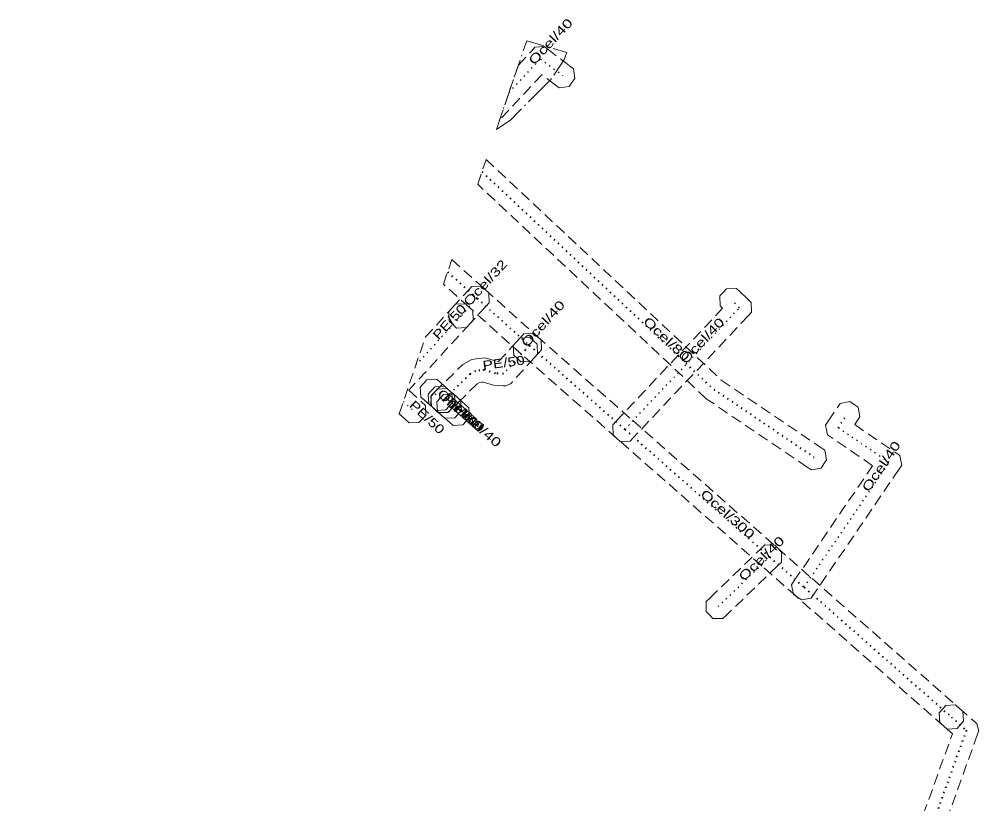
# Model space of a CAD drawing. Extents: x -644301 to -644150, y -1042432 to -1042139.
# Drawn here: x -644293 to -644212.5, y -1042204.6 to -1042138.8 of the extents above; entities that cross this region are included whole.
import ezdxf

# ---------------------------------------------------------------- set-up
doc = ezdxf.new("R2010")
doc.units = 0
doc.header["$LTSCALE"] = 0.3
for name, pattern in [('DOT_DASHED', [7.7, 5, -1.2, 0.3, -1.2]), ('DOTTED', [1.5, 0.3, -1.2]), ('MEDIUM_DASHED', [4.5, 3, -1.5])]:
    doc.linetypes.add(name, pattern=pattern)
for name, color, linetype, lineweight in [('1', 7, 'MEDIUM_DASHED', 13), ('18', 7, 'DOTTED', 25), ('3', 7, 'DOT_DASHED', 13)]:
    doc.layers.add(name, color=color, linetype=linetype, lineweight=lineweight)
doc.layers.add('20', color=7, linetype='Continuous')

msp = doc.modelspace()

# ---------------------------------------------------------------- linework, layer by layer
at = {"layer": '1'}
for points in [[(-644249.115, -1042143.464), (-644252.666, -1042147.268), (-644251.086, -1042142.644), (-644249.963, -1042141.441), (-644249.701, -1042141.16), (-644248.937, -1042141.094), (-644248.63, -1042141.325), (-644246.79, -1042142.713), (-644246.459, -1042142.962), (-644246.344, -1042143.782), (-644246.594, -1042144.113), (-644246.843, -1042144.444), (-644247.663, -1042144.559), (-644247.994, -1042144.309)], [(-644235.331, -1042170.644), (-644254.504, -1042152.644), (-644253.794, -1042150.568), (-644234.077, -1042169.078), (-644225.728, -1042174.736), (-644225.385, -1042174.968), (-644225.229, -1042175.782), (-644225.461, -1042176.125), (-644225.693, -1042176.468), (-644226.507, -1042176.624), (-644226.85, -1042176.392)], [(-644255.22, -1042162.968), (-644257.371, -1042161.031), (-644256.667, -1042158.974), (-644253.882, -1042161.482), (-644249.504, -1042165.424), (-644241.501, -1042172.475), (-644229.358, -1042183.173), (-644226.458, -1042185.728), (-644214.106, -1042196.61), (-644213.795, -1042196.884), (-644213.743, -1042197.71), (-644214.017, -1042198.021), (-644214.291, -1042198.332), (-644215.117, -1042198.384), (-644215.428, -1042198.11), (-644227.78, -1042187.228), (-644230.68, -1042184.673), (-644242.823, -1042173.975), (-644250.834, -1042166.918)], [(-644253.535, -1042162.597), (-644253.815, -1042162.902), (-644255.168, -1042164.374), (-644255.448, -1042164.679), (-644256.276, -1042164.713), (-644256.581, -1042164.433), (-644256.886, -1042164.153), (-644256.92, -1042163.325), (-644256.64, -1042163.02), (-644255.287, -1042161.548), (-644255.007, -1042161.243), (-644254.179, -1042161.209), (-644253.874, -1042161.489), (-644253.569, -1042161.769)], [(-644242.89, -1042172.54), (-644233.955, -1042163.05), (-644234.166, -1042162.852), (-644234.19, -1042162.024), (-644233.906, -1042161.722), (-644233.622, -1042161.42), (-644232.794, -1042161.396), (-644232.492, -1042161.68), (-644231.856, -1042162.279), (-644231.555, -1042162.563), (-644231.53, -1042163.391), (-644231.814, -1042163.692), (-644241.434, -1042173.91), (-644241.718, -1042174.212), (-644242.545, -1042174.237), (-644242.847, -1042173.953), (-644243.149, -1042173.669), (-644243.174, -1042172.842)], [(-644260.559, -1042172.397), (-644261.087, -1042171.906), (-644258.885, -1042165.462), (-644256.64, -1042163.02), (-644256.36, -1042162.715), (-644255.532, -1042162.681), (-644255.227, -1042162.961), (-644254.922, -1042163.241), (-644254.888, -1042164.069), (-644255.168, -1042164.374), (-644260.275, -1042169.93), (-644259.197, -1042170.933), (-644258.894, -1042171.215), (-644258.864, -1042172.043), (-644259.146, -1042172.346), (-644259.428, -1042172.649), (-644260.256, -1042172.679)], [(-644249.486, -1042166.906), (-644249.765, -1042167.213), (-644251.593, -1042169.227), (-644251.743, -1042169.392), (-644252.155, -1042169.564), (-644252.378, -1042169.554), (-644253.177, -1042169.518), (-644254.057, -1042169.245), (-644254.185, -1042169.262), (-644254.356, -1042169.285), (-644254.547, -1042169.392), (-644256.716, -1042171.522), (-644257.012, -1042171.812), (-644257.84, -1042171.805), (-644258.13, -1042171.51), (-644258.42, -1042171.214), (-644258.413, -1042170.386), (-644258.118, -1042170.096), (-644255.757, -1042167.776), (-644254.998, -1042167.353), (-644254.449, -1042167.28), (-644253.885, -1042167.205), (-644252.831, -1042167.532), (-644252.758, -1042167.535), (-644251.245, -1042165.869), (-644250.967, -1042165.562), (-644250.14, -1042165.522), (-644249.833, -1042165.801), (-644249.526, -1042166.079)], [(-644249.15, -1042166.536), (-644249.429, -1042166.843), (-644249.765, -1042167.213), (-644250.043, -1042167.52), (-644250.87, -1042167.56), (-644251.177, -1042167.281), (-644251.484, -1042167.003), (-644251.524, -1042166.176), (-644251.245, -1042165.869), (-644250.909, -1042165.499), (-644250.631, -1042165.192), (-644249.804, -1042165.152), (-644249.497, -1042165.431), (-644249.19, -1042165.709)], [(-644257.992, -1042171.636), (-644258.302, -1042171.361), (-644258.957, -1042170.78), (-644259.267, -1042170.505), (-644259.316, -1042169.678), (-644259.041, -1042169.368), (-644258.766, -1042169.058), (-644257.939, -1042169.009), (-644257.629, -1042169.284), (-644256.974, -1042169.865), (-644256.664, -1042170.14), (-644256.615, -1042170.967), (-644256.89, -1042171.277), (-644257.165, -1042171.587)], [(-644257.771, -1042171.832), (-644258.081, -1042171.557), (-644258.302, -1042171.361), (-644258.612, -1042171.086), (-644258.661, -1042170.259), (-644258.386, -1042169.949), (-644258.111, -1042169.639), (-644257.284, -1042169.59), (-644256.974, -1042169.865), (-644256.753, -1042170.061), (-644256.443, -1042170.336), (-644256.394, -1042171.163), (-644256.669, -1042171.473), (-644256.944, -1042171.783)], [(-644257.063, -1042169.786), (-644256.753, -1042170.061), (-644256.236, -1042170.52), (-644255.926, -1042170.795), (-644255.877, -1042171.622), (-644256.152, -1042171.932), (-644256.427, -1042172.242), (-644257.254, -1042172.291), (-644257.564, -1042172.016), (-644258.081, -1042171.557), (-644258.391, -1042171.282), (-644258.44, -1042170.455), (-644258.165, -1042170.145), (-644257.89, -1042169.835)], [(-644256.542, -1042170.247), (-644256.233, -1042170.523), (-644256.15, -1042170.597), (-644255.549, -1042171.129), (-644255.239, -1042171.404), (-644255.188, -1042172.231), (-644255.463, -1042172.541), (-644255.738, -1042172.851), (-644256.565, -1042172.902), (-644256.875, -1042172.627), (-644257.48, -1042172.091), (-644257.567, -1042172.013), (-644257.876, -1042171.737), (-644257.921, -1042170.91), (-644257.645, -1042170.601), (-644257.369, -1042170.292)], [(-644228.178, -1042186.257), (-644227.945, -1042185.915), (-644221.372, -1042176.267), (-644224.829, -1042173.912), (-644225.171, -1042173.679), (-644225.249, -1042173.272), (-644225.326, -1042172.865), (-644225.092, -1042172.523), (-644224.319, -1042171.389), (-644224.086, -1042171.046), (-644223.272, -1042170.892), (-644222.93, -1042171.126), (-644222.587, -1042171.359), (-644222.433, -1042172.173), (-644222.667, -1042172.515), (-644222.876, -1042172.823), (-644219.42, -1042175.178), (-644219.078, -1042175.411), (-644219, -1042175.818), (-644218.923, -1042176.225), (-644219.157, -1042176.567), (-644226.293, -1042187.041), (-644226.526, -1042187.383), (-644227.34, -1042187.537), (-644227.682, -1042187.304), (-644228.024, -1042187.071)], [(-644235.327, -1042187.662), (-644235.029, -1042187.374), (-644230.714, -1042183.204), (-644230.416, -1042182.916), (-644229.588, -1042182.93), (-644229.3, -1042183.228), (-644229.012, -1042183.526), (-644229.026, -1042184.354), (-644229.324, -1042184.642), (-644233.639, -1042188.812), (-644233.937, -1042189.1), (-644234.765, -1042189.086), (-644235.053, -1042188.788), (-644235.341, -1042188.49)]]:
    msp.add_lwpolyline(points, close=True, dxfattribs=at)
msp.add_lwpolyline([(-644250.393, -1042294.532), (-644239.756, -1042268.927), (-644236.811, -1042260.588), (-644229.493, -1042239.868), (-644228.876, -1042238.156), (-644222.16, -1042219.521), (-644214.681, -1042198.769), (-644215.428, -1042198.11), (-644215.739, -1042197.836), (-644215.791, -1042197.01), (-644215.517, -1042196.699), (-644215.243, -1042196.388), (-644214.417, -1042196.336), (-644214.106, -1042196.61), (-644212.849, -1042197.718), (-644212.618, -1042197.921), (-644212.465, -1042198.517), (-644212.569, -1042198.807), (-644220.278, -1042220.199), (-644226.994, -1042238.834), (-644227.609, -1042240.54), (-644234.925, -1042261.254), (-644237.888, -1042269.645), (-644248.531, -1042295.264)], dxfattribs=at)
at = {"layer": '18'}
for p, q in [((-644254.551, -1042162.225), (-644255.904, -1042163.697)), ((-644255.904, -1042163.697), (-644259.689, -1042167.814)), ((-644257.638, -1042170.613), (-644258.293, -1042170.032)), ((-644257.417, -1042170.809), (-644257.638, -1042170.613)), ((-644260.733, -1042170.87), (-644259.878, -1042171.665)), ((-644257.417, -1042170.809), (-644256.9, -1042171.268)), ((-644234.334, -1042188.093), (-644230.019, -1042183.923))]:
    msp.add_line(p, q, dxfattribs=at)
at = {"layer": '18', "lineweight": 40}
msp.add_line((-644250.169, -1042166.171), (-644250.505, -1042166.541), dxfattribs=at)
at = {"layer": '18'}
for points in [[(-644251.876, -1042144.955), (-644249.232, -1042142.123), (-644247.392, -1042143.511)], [(-644242.162, -1042173.225), (-644232.542, -1042163.007), (-644233.178, -1042162.408)], [(-644256.9, -1042171.268), (-644256.815, -1042171.344), (-644256.212, -1042171.878)], [(-644227.119, -1042186.478), (-644219.983, -1042176.004), (-644224.266, -1042173.086), (-644223.493, -1042171.952)]]:
    msp.add_lwpolyline(points, dxfattribs=at)
at = {"layer": '18', "lineweight": 40}
for points in [[(-644254.149, -1042151.606), (-644234.704, -1042169.861), (-644226.289, -1042175.564)], [(-644257.019, -1042160.003), (-644254.551, -1042162.225), (-644250.169, -1042166.171), (-644242.162, -1042173.225), (-644230.019, -1042183.923), (-644227.119, -1042186.478), (-644214.767, -1042197.36)], [(-644250.505, -1042166.541), (-644252.333, -1042168.555), (-644253.004, -1042168.525), (-644253.971, -1042168.225), (-644254.317, -1042168.271), (-644254.677, -1042168.319), (-644255.152, -1042168.584), (-644257.417, -1042170.809)], [(-644214.767, -1042197.36), (-644213.51, -1042198.468), (-644221.219, -1042219.86), (-644227.935, -1042238.495), (-644228.551, -1042240.204), (-644235.868, -1042260.921), (-644238.822, -1042269.286), (-644249.462, -1042294.898), (-644253.663, -1042306.177), (-644265.37, -1042336.505), (-644273.598, -1042358.025), (-644285.881, -1042390.152), (-644286.759, -1042395.281), (-644289.198, -1042409.522), (-644292.966, -1042431.522)]]:
    msp.add_lwpolyline(points, dxfattribs=at)
at = {"layer": '3'}
msp.add_lwpolyline([(-644251.733, -1042147.237), (-644252.932, -1042148.045), (-644250.39, -1042140.607), (-644247.022, -1042141.581), (-644247.29, -1042142.236), (-644248.393, -1042143.893), (-644249.097, -1042144.597), (-644249.178, -1042144.678), (-644251.048, -1042146.551)], close=True, dxfattribs=at)

# ---------------------------------------------------------------- texts
at = {"layer": '20'}
for s, rotation, width, p in [('Ocel/40', 46.967, 1.4, (-644249.768, -1042142.697)), ('Ocel/32', 47.412, 1.4, (-644255.228, -1042162.961)), ('Ocel/40', 47.757, 1.4, (-644250.371, -1042166.393)), ('PE/50', 47.41, 1.3, (-644257.797, -1042165.755)), ('Ocel/80', 316.808, 1.4, (-644240.684, -1042164.246)), ('Ocel/40', 46.727, 1.4, (-644237.053, -1042167.798)), ('PE/50', 7.573, 1.3, (-644254.034, -1042168.233)), ('Ocel/40', 318.426, 1.4, (-644257.965, -1042170.322)), ('PE/50', 318.431, 1.3, (-644257.527, -1042170.711)), ('PE/50', 318.401, 1.3, (-644257.158, -1042171.038)), ('PE/50', 317.071, 1.3, (-644260.305, -1042171.267)), ('Ocel/40', 318.473, 1.4, (-644256.556, -1042171.573)), ('Ocel/40', 55.733, 1.4, (-644221.706, -1042178.532)), ('Ocel/300', 318.62, 1.4, (-644235.889, -1042178.752)), ('Ocel/40', 44.021, 1.4, (-644232.177, -1042186.008))]:
    msp.add_text(s, height=0.75, rotation=rotation, dxfattribs=dict(at, width=width)).set_placement(p)

doc.saveas('drawing.dxf')
